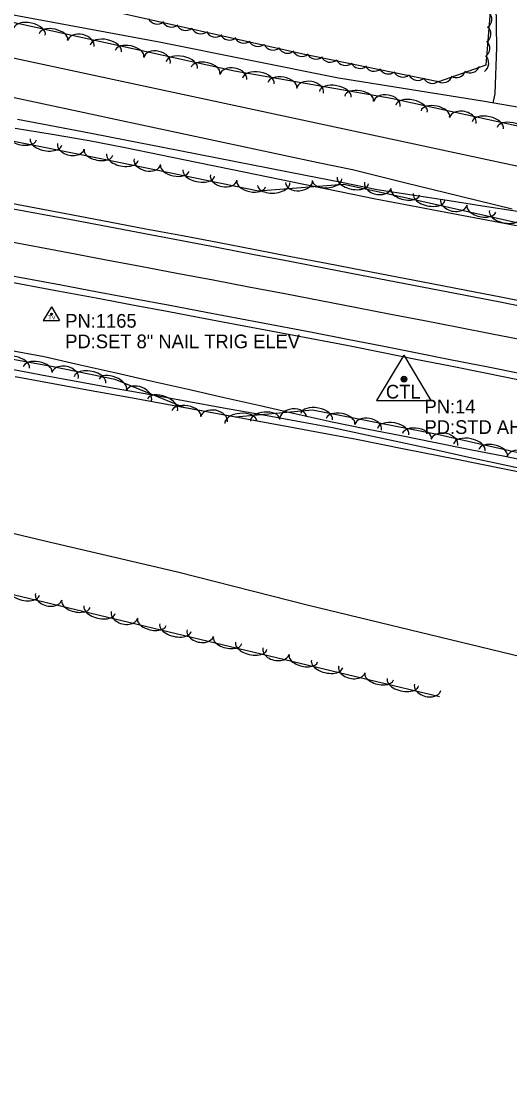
# Model space of a CAD drawing. Extents: x 1441650 to 1491889, y 345904 to 358319.
# Drawn here: x 1456782.8 to 1456961.1, y 351630.1 to 352014.8 of the extents above; entities that cross this region are included whole.
import ezdxf

# ---------------------------------------------------------------- set-up
doc = ezdxf.new("R2010")
doc.units = 0
for name, color, linetype in [('S_DITCHLINE', 7, 'Continuous'), ('S_EDGE_PAVEMENT', 7, 'Continuous'), ('S_PAVEMENT_CROWN', 7, 'Continuous'), ('S_PRIMARY_CTL', 7, 'Continuous'), ('S_PRIMARY_CTL_ANNOT', 7, 'Continuous'), ('S_SECONDARY_CTL', 7, 'Continuous'), ('S_SECONDARY_CTL_ANNOT', 7, 'Continuous'), ('S_SHOULDER', 7, 'Continuous'), ('S_STREAM', 7, 'Continuous'), ('S_TRAILS', 7, 'Continuous'), ('S_TREE', 7, 'Continuous'), ('S_WATER_UTILITIES', 7, 'Continuous')]:
    doc.layers.add(name, color=color, linetype=linetype)

msp = doc.modelspace()

# ---------------------------------------------------------------- linework, layer by layer
at = {"layer": 'S_DITCHLINE'}
for points in [[(1456781.58, 351979.01), (1456795, 351976.49), (1456808.42, 351973.98), (1456821.45, 351971.42), (1456834.49, 351968.85), (1456847.52, 351966.28), (1456860.55, 351963.72), (1456873.59, 351961.15), (1456886.62, 351958.58), (1456899.65, 351956.02), (1456912.68, 351953.45), (1456925.49, 351951.47), (1456938.3, 351949.49), (1456951.11, 351947.5), (1456963.92, 351945.52)], [(1456780.67, 351975.73), (1456794.2, 351973.53), (1456807.73, 351971.33), (1456820.78, 351968.67), (1456833.82, 351966), (1456846.87, 351963.33), (1456859.92, 351960.67), (1456872.97, 351958), (1456886.02, 351955.33), (1456899.07, 351952.67), (1456912.12, 351950), (1456924.96, 351947.57), (1456937.81, 351945.14), (1456950.66, 351942.71), (1456963.5, 351940.28)], [(1456777.96, 351894.89), (1456791.27, 351892.43), (1456804.39, 351889.45), (1456817.51, 351886.48), (1456830.63, 351883.51), (1456843.75, 351880.54), (1456856.87, 351877.56), (1456869.99, 351874.59), (1456883.12, 351871.62), (1456896.24, 351868.64), (1456908.83, 351866.13), (1456921.43, 351863.62), (1456934.03, 351861.11), (1456946.62, 351858.6), (1456959.22, 351856.09), (1456971.81, 351853.58)], [(1456776.87, 351888.36), (1456790.32, 351885.77), (1456803.58, 351883.38), (1456816.85, 351880.98), (1456830.12, 351878.59), (1456843.38, 351876.19), (1456856.65, 351873.79), (1456869.91, 351871.4), (1456883.18, 351869), (1456896.45, 351866.61), (1456908.88, 351863.91), (1456921.32, 351861.21), (1456933.76, 351858.5), (1456946.19, 351855.8), (1456958.63, 351853.1), (1456971.07, 351850.4)]]:
    msp.add_lwpolyline(points, dxfattribs=at)
at = {"layer": 'S_EDGE_PAVEMENT'}
for points in [[(1456778.58, 351946.61), (1456801.15, 351942.44), (1456814.57, 351939.9), (1456827.99, 351937.36), (1456841.41, 351934.82), (1456854.83, 351932.28), (1456867.86, 351929.74), (1456880.89, 351927.2), (1456893.92, 351924.67), (1456906.95, 351922.13), (1456919.61, 351919.71), (1456932.26, 351917.28), (1456944.92, 351914.86), (1456957.57, 351912.44), (1456970.03, 351909.93)], [(1456774.91, 351922.81), (1456797.44, 351918.6), (1456810.67, 351916.12), (1456823.9, 351913.65), (1456837.14, 351911.17), (1456850.37, 351908.69), (1456863.25, 351906.24), (1456876.13, 351903.78), (1456889.02, 351901.32), (1456901.9, 351898.86), (1456914.58, 351896.35), (1456927.27, 351893.83), (1456939.95, 351891.32), (1456952.64, 351888.8), (1456965.25, 351886.28)]]:
    msp.add_lwpolyline(points, dxfattribs=at)
at = {"layer": 'S_PAVEMENT_CROWN'}
msp.add_lwpolyline([(1456776.85, 351934.76), (1456800.01, 351930.39), (1456813.21, 351927.91), (1456826.42, 351925.43), (1456839.63, 351922.94), (1456852.84, 351920.46), (1456865.95, 351917.94), (1456879.06, 351915.42), (1456892.17, 351912.9), (1456905.29, 351910.38), (1456917.64, 351907.97), (1456930, 351905.57), (1456942.35, 351903.16), (1456954.7, 351900.75), (1456967.29, 351898.27)], dxfattribs=at)
at = {"layer": 'S_PRIMARY_CTL'}
for p, q in [((1456922.49, 351892.93), (1456912.46, 351876.42)), ((1456922.49, 351892.93), (1456932.31, 351876.42)), ((1456912.46, 351876.42), (1456932.31, 351876.42))]:
    msp.add_line(p, q, dxfattribs=at)
for radius in [1.04, 0.609, 0.344]:
    msp.add_circle((1456922.49, 351884.23), radius, dxfattribs=at)
at = {"layer": 'S_SECONDARY_CTL'}
for p, q in [((1456793.96, 351910.6), (1456790.95, 351905.64)), ((1456793.96, 351910.6), (1456796.91, 351905.64)), ((1456790.95, 351905.64), (1456796.91, 351905.64))]:
    msp.add_line(p, q, dxfattribs=at)
for radius in [0.311, 0.183, 0.103]:
    msp.add_circle((1456793.96, 351907.99), radius, dxfattribs=at)
at = {"layer": 'S_SHOULDER'}
for points in [[(1456779.26, 351948.41), (1456801.68, 351944.19), (1456815.03, 351941.65), (1456828.39, 351939.1), (1456841.75, 351936.56), (1456855.1, 351934.01), (1456868.16, 351931.5), (1456881.22, 351928.99), (1456894.29, 351926.47), (1456907.35, 351923.96), (1456919.97, 351921.52), (1456932.6, 351919.08), (1456945.23, 351916.64), (1456957.86, 351914.2), (1456970.43, 351911.7)], [(1456774.68, 351920.5), (1456796.91, 351916.32), (1456810.18, 351913.83), (1456823.44, 351911.34), (1456836.71, 351908.85), (1456849.97, 351906.36), (1456862.9, 351903.91), (1456875.83, 351901.46), (1456888.76, 351899.02), (1456901.69, 351896.57), (1456914.28, 351894.07), (1456926.87, 351891.56), (1456939.46, 351889.05), (1456952.05, 351886.54), (1456964.63, 351884.02)]]:
    msp.add_lwpolyline(points, dxfattribs=at)
at = {"layer": 'S_STREAM'}
msp.add_lwpolyline([(1456615.77, 351865.35), (1456695.66, 351848.16), (1456791.55, 351825.27), (1456839.87, 351813.99), (1456887.66, 351801.8), (1456991.3, 351776.75), (1457048.85, 351760.81), (1457118.67, 351745.25)], dxfattribs=at)
at = {"layer": 'S_TRAILS'}
for points in [[(1457268.76, 352049.42), (1457263.88, 352006.18), (1457257.72, 351978.65), (1457254.6, 351968.16), (1457245.15, 351954.83), (1457236.81, 351943.99), (1457223.45, 351940.54), (1457207.24, 351942.59), (1457150.06, 351951.48), (1457102.66, 351954.44), (1457056.72, 351964.71), (1457003.28, 351976.66), (1456951.11, 351985.66), (1456898.64, 351994), (1456833.2, 352007.16), (1456729.36, 352026.45), (1456653.98, 352040.61), (1456597.16, 352049.77), (1456529.59, 352059.81), (1456484.15, 352069.96), (1456466.33, 352073.63), (1456452.89, 352073.26), (1456447.05, 352071.68)], [(1456955.79, 352036.95), (1456956.2, 352005.22), (1456955.65, 351988.47), (1456954.84, 351984.84)]]:
    msp.add_lwpolyline(points, dxfattribs=at)
at = {"layer": 'S_TREE'}
for points in [[(1456527.22, 352219.77), (1456540.48, 352171.06), (1456547.01, 352136.18), (1456543.07, 352095.02), (1456540.96, 352069.62), (1456549.68, 352052.53), (1456572.48, 352046.22), (1456656.69, 352034.98), (1456766.41, 352017.4), (1456860.65, 351996.7), (1456917.81, 351986.67), (1456968.36, 351975.61), (1457003.67, 351974.34), (1457037, 351966.87), (1457091.18, 351954.76), (1457133.43, 351949.73), (1457169.05, 351946.81), (1457212.77, 351938.5), (1457241.33, 351937.88), (1457252.05, 351948.92), (1457259.75, 351971.53), (1457265.42, 351993.28), (1457268.88, 352004.52)], [(1456946.77, 352049.56), (1456954, 352019.61), (1456952.33, 351998.8), (1456935.11, 351992.63), (1456885.1, 352002.92), (1456810.32, 352019.63), (1456765.4, 352029.56), (1456649.16, 352049.43), (1456604.07, 352059.51), (1456562.66, 352066.04), (1456541.64, 352068)], [(1457347.72, 351846.82), (1457259.29, 351869.82), (1457150.71, 351895.35), (1457088.32, 351909.3), (1456973.99, 351938.99), (1456924.65, 351950.02), (1456900.56, 351955.26), (1456869.4, 351952.76), (1456813.77, 351964.27), (1456707.01, 351985.55), (1456663.97, 352001.96), (1456648.9, 352003.9), (1456628.29, 351995.91)], [(1456778.58, 351987.33), (1456791.1, 351984.66), (1456803.61, 351981.99), (1456816.12, 351979.32), (1456828.63, 351976.65), (1456841.14, 351973.98), (1456853.65, 351971.31), (1456866.17, 351968.64), (1456878.68, 351965.97), (1456891.19, 351963.3), (1456903.7, 351960.64), (1456923.13, 351955.87), (1456942.57, 351951.11), (1456962, 351946.35)], [(1456778.58, 351987.33), (1456791.1, 351984.66), (1456803.61, 351981.99), (1456816.12, 351979.32), (1456828.63, 351976.65), (1456841.14, 351973.98), (1456853.65, 351971.31), (1456866.17, 351968.64), (1456878.68, 351965.97), (1456891.19, 351963.3), (1456903.7, 351960.64), (1456923.13, 351955.87), (1456942.57, 351951.11), (1456962, 351946.35)], [(1456598.75, 351924.13), (1456686.06, 351910.97), (1456743.52, 351898.13), (1456793.9, 351888.95), (1456816.98, 351884.21), (1456842.02, 351874.01), (1456861.09, 351870.49), (1456889.07, 351872.98), (1456934.56, 351864.11), (1456964.71, 351857.37), (1457007.79, 351847.74), (1457051.75, 351837.91), (1457091.09, 351829.12), (1457165.52, 351812.48), (1457202.07, 351804.31), (1457267.07, 351790.49), (1457300, 351783.98), (1457347.16, 351770.87), (1457399.34, 351758.41), (1457426.78, 351748.95), (1457472.56, 351738.71), (1457528.33, 351726.24), (1457565.01, 351719.11), (1457614.77, 351707.89)], [(1456780.68, 351885.2), (1456794.51, 351882.66), (1456808.35, 351880.12), (1456822.18, 351877.59), (1456836.02, 351875.05), (1456849.85, 351872.51), (1456863.69, 351869.98), (1456877.52, 351867.44), (1456891.35, 351864.9), (1456905.19, 351862.36), (1456923.18, 351858.74), (1456941.17, 351855.11), (1456959.16, 351851.48), (1456977.15, 351847.85)], [(1456780.68, 351885.2), (1456794.51, 351882.66), (1456808.35, 351880.12), (1456822.18, 351877.59), (1456836.02, 351875.05), (1456849.85, 351872.51), (1456863.69, 351869.98), (1456877.52, 351867.44), (1456891.35, 351864.9), (1456905.19, 351862.36), (1456923.18, 351858.74), (1456941.17, 351855.11), (1456959.16, 351851.48), (1456977.15, 351847.85)], [(1456935.41, 351768.32), (1456757.49, 351810.91), (1456654.24, 351836.69), (1456612.99, 351855.17), (1456594.02, 351860.27), (1456573.25, 351864.94)]]:
    msp.add_lwpolyline(points, dxfattribs=at)
for centre, start, end in [((1456950.93, 352015.49), 304.6102, 46.2072), ((1456832.54, 352017.39), 206.6009, 308.1978), ((1456837.71, 352016.31), 206.6009, 308.1978), ((1456842.9, 352015.08), 206.6009, 308.1978), ((1456848.4, 352013.81), 206.6009, 308.1978), ((1456853.71, 352012.62), 206.6009, 308.1978), ((1456858.89, 352011.5), 206.6009, 308.1978), ((1456950.58, 352010.22), 304.6102, 46.2072), ((1456864.07, 352010.42), 206.6009, 308.1978), ((1456869.26, 352009.19), 206.6009, 308.1978), ((1456874.76, 352007.92), 206.6009, 308.1978), ((1456950.19, 352004.93), 304.6102, 46.2072), ((1456880.07, 352006.73), 206.6009, 308.1978), ((1456885.25, 352005.61), 206.6009, 308.1978), ((1456890.39, 352004.62), 207.5781, 309.175), ((1456949.75, 351999.5), 304.6102, 46.2072), ((1456895.61, 352003.47), 207.5781, 309.175), ((1456901.13, 352002.3), 207.5781, 309.175), ((1456906.46, 352001.2), 207.5781, 309.175), ((1456911.66, 352000.17), 207.5781, 309.175), ((1456946.58, 351999.57), 238.9264, 340.5233), ((1456916.85, 351999.18), 207.5781, 309.175), ((1456922.06, 351998.03), 207.5781, 309.175), ((1456927.58, 351996.86), 207.5781, 309.175), ((1456936.59, 351995.99), 238.9264, 340.5233), ((1456941.53, 351997.84), 238.9264, 340.5233), ((1456932.91, 351995.76), 207.5781, 309.175)]:
    msp.add_arc(centre, 3.64, start, end, dxfattribs=at)
for centre, major_axis, ratio, start_param, end_param in [((1456785.95, 352010.94), (-5.73, 1.26), 0.55008, 3.141593, 6.283185), ((1456794.61, 352009.04), (-5.22, 1.15), 0.540699, 3.141593, 6.283185), ((1456804.62, 352006.57), (-4.84, 1.06), 0.685311, 3.141593, 6.283185), ((1456813.72, 352004.84), (-5.73, 1.26), 0.55008, 3.141593, 6.283185), ((1456822.38, 352002.94), (-5.22, 1.15), 0.540699, 3.141593, 6.283185), ((1456832.39, 352000.47), (-4.84, 1.06), 0.685311, 3.141593, 6.283185), ((1456841.48, 351998.74), (-5.73, 1.26), 0.55008, 3.141593, 6.283185), ((1456850.15, 351996.84), (-5.22, 1.15), 0.540699, 3.141593, 6.283185), ((1456860.25, 351994.35), (-4.88, 0.86), 0.685311, 3.141593, 6.283185), ((1456869.41, 351993.01), (-5.78, 1.01), 0.55008, 3.141593, 6.283185), ((1456878.15, 351991.48), (-5.27, 0.92), 0.540699, 3.141593, 6.283185), ((1456888.25, 351989.44), (-4.88, 0.86), 0.685311, 3.141593, 6.283185), ((1456897.41, 351988.09), (-5.78, 1.01), 0.55008, 3.141593, 6.283185), ((1456906.15, 351986.56), (-5.27, 0.92), 0.540699, 3.141593, 6.283185), ((1456916.25, 351984.52), (-4.88, 0.86), 0.685311, 3.141593, 6.283185), ((1456925.26, 351982.86), (-5.73, 1.25), 0.550095, 3.141595, 6.283187), ((1456933.92, 351980.97), (-5.22, 1.14), 0.540714, 3.141595, 6.283187), ((1456943.93, 351978.51), (-4.84, 1.06), 0.685329, 3.141596, 6.283189), ((1456953.03, 351976.79), (-5.73, 1.25), 0.550095, 3.141595, 6.283187), ((1456961.69, 351974.89), (-5.22, 1.14), 0.540714, 3.141595, 6.283187), ((1456783.2, 351972.51), (5.24, -1.05), 0.536291, 3.141565, 6.283158), ((1456791.9, 351970.77), (5.76, -1.15), 0.545595, 3.141564, 6.283157), ((1456801.03, 351969.22), (4.86, -0.97), 0.679723, 3.141546, 6.283139), ((1456811.08, 351966.95), (5.24, -1.05), 0.536291, 3.141565, 6.283158), ((1456819.78, 351965.17), (5.75, -1.19), 0.545599, 3.141538, 6.283131), ((1456828.9, 351963.55), (4.85, -1), 0.679728, 3.141504, 6.283096), ((1456838.94, 351961.21), (5.24, -1.08), 0.536295, 3.14154, 6.283132), ((1456847.62, 351959.41), (5.75, -1.19), 0.545599, 3.141538, 6.283131), ((1456856.74, 351957.79), (4.85, -1), 0.679728, 3.141504, 6.283096), ((1456866.78, 351955.45), (5.24, -1.08), 0.536295, 3.14154, 6.283132), ((1456874.97, 351955.31), (5.85, 0.48), 0.545931, 3.139332, 6.280925), ((1456884.18, 351956.31), (4.94, 0.41), 0.68014, 3.137914, 6.279506), ((1456894.46, 351956.88), (5.33, 0.43), 0.536621, 3.139402, 6.280995), ((1456903.86, 351956.69), (5.73, -1.24), 0.545725, 3.139485, 6.281078), ((1456912.96, 351954.98), (4.84, -1.04), 0.679883, 3.138164, 6.279757), ((1456922.97, 351952.53), (5.22, -1.13), 0.536419, 3.13955, 6.281143), ((1456931.63, 351950.61), (5.73, -1.28), 0.545634, 3.140627, 6.28222), ((1456940.72, 351948.84), (4.84, -1.08), 0.679772, 3.140022, 6.281615), ((1456950.72, 351946.34), (5.22, -1.16), 0.53633, 3.140657, 6.28225), ((1456959.37, 351944.41), (5.73, -1.28), 0.545634, 3.140627, 6.28222), ((1456780.14, 351889.31), (-5.77, 1.05), 0.546951, 3.141593, 6.283185), ((1456788.86, 351887.73), (-5.26, 0.96), 0.537624, 3.141593, 6.283185), ((1456798.87, 351885.51), (-4.85, 1), 0.68142, 3.141143, 6.282736), ((1456807.99, 351883.9), (-5.75, 1.18), 0.546957, 3.141317, 6.28291), ((1456816.3, 351882.21), (-4.95, 2.02), 0.53776, 3.141593, 6.283185), ((1456825.74, 351878.08), (-4.59, 1.87), 0.681585, 3.141593, 6.283185), ((1456834.42, 351874.82), (-5.43, 2.21), 0.547089, 3.141593, 6.283185), ((1456843.13, 351871.66), (-5.26, 0.97), 0.537625, 3.141593, 6.283185), ((1456853.21, 351869.53), (-4.87, 0.9), 0.681414, 3.141593, 6.283185), ((1456862.96, 351868.54), (-5.85, -0.52), 0.547162, 3.141593, 6.283185), ((1456871.79, 351869.33), (-5.33, -0.47), 0.537831, 3.141593, 6.283185), ((1456882.07, 351869.98), (-4.94, -0.44), 0.681676, 3.141593, 6.283185), ((1456890.65, 351870.53), (-5.76, 1.12), 0.546952, 3.141593, 6.283185), ((1456899.35, 351868.83), (-5.25, 1.02), 0.537625, 3.141593, 6.283185), ((1456909.42, 351866.6), (-4.86, 0.95), 0.681415, 3.141593, 6.283185), ((1456918.55, 351865.08), (-5.76, 1.12), 0.546952, 3.141593, 6.283185), ((1456927.26, 351863.38), (-5.25, 1.02), 0.537625, 3.141593, 6.283185), ((1456937.24, 351861.08), (-4.84, 1.08), 0.681421, 3.141593, 6.283185), ((1456946.33, 351859.31), (-5.73, 1.28), 0.546958, 3.141593, 6.283185), ((1456954.98, 351857.38), (-5.22, 1.17), 0.537631, 3.141593, 6.283185), ((1456964.98, 351854.88), (-4.84, 1.08), 0.681421, 3.141593, 6.283185), ((1456783.85, 351806.78), (5.71, -1.37), 0.549745, 3.141752, 6.283345), ((1456792.91, 351804.88), (4.82, -1.15), 0.684894, 3.141854, 6.283447), ((1456802.87, 351802.23), (5.2, -1.25), 0.540371, 3.141747, 6.28334), ((1456811.49, 351800.16), (5.71, -1.37), 0.549745, 3.141752, 6.283345), ((1456820.56, 351798.26), (4.82, -1.15), 0.684894, 3.141854, 6.283447), ((1456830.51, 351795.61), (5.2, -1.25), 0.540371, 3.141747, 6.28334), ((1456839.14, 351793.55), (5.71, -1.37), 0.549745, 3.141752, 6.283345), ((1456848.2, 351791.64), (4.82, -1.15), 0.684894, 3.141854, 6.283447), ((1456858.16, 351788.99), (5.2, -1.25), 0.540371, 3.141747, 6.28334), ((1456866.78, 351786.93), (5.71, -1.37), 0.549745, 3.141752, 6.283345), ((1456875.85, 351785.03), (4.82, -1.15), 0.684894, 3.141854, 6.283447), ((1456885.81, 351782.37), (5.2, -1.25), 0.540371, 3.141747, 6.28334), ((1456894.43, 351780.31), (5.71, -1.37), 0.549745, 3.141752, 6.283345), ((1456903.49, 351778.41), (4.82, -1.15), 0.684894, 3.141854, 6.283447), ((1456913.45, 351775.76), (5.2, -1.25), 0.540371, 3.141747, 6.28334), ((1456922.08, 351773.69), (5.71, -1.37), 0.549745, 3.141752, 6.283345), ((1456931.14, 351771.79), (4.82, -1.15), 0.684894, 3.141854, 6.283447)]:
    msp.add_ellipse(centre, major_axis=major_axis, ratio=ratio, start_param=start_param, end_param=end_param, dxfattribs=at)
at = {"layer": 'S_WATER_UTILITIES'}
msp.add_line((1456494.84, 352062.52), (1458511.04, 351630.06), dxfattribs=at)

# ---------------------------------------------------------------- texts
at = {"layer": 'S_PRIMARY_CTL'}
msp.add_text('CTL', height=5, rotation=360, dxfattribs=at).set_placement((1456915.9, 351877.15))
at = {"layer": 'S_PRIMARY_CTL_ANNOT'}
for s, p in [('PN:14', (1456929.99, 351871.73)), ('PD:STD AHTD MON.STAMPED PN:14 JOB 050264', (1456929.99, 351864.23))]:
    msp.add_text(s, height=5, dxfattribs=at).set_placement(p)
at = {"layer": 'S_SECONDARY_CTL'}
msp.add_text('TV', height=1.5, rotation=360, dxfattribs=at).set_placement((1456792.76, 351905.98))
at = {"layer": 'S_SECONDARY_CTL_ANNOT'}
for s, p in [('PN:1165', (1456798.96, 351902.99)), ('PD:SET 8" NAIL TRIG ELEV', (1456798.96, 351895.49))]:
    msp.add_text(s, height=5, dxfattribs=at).set_placement(p)

doc.saveas('drawing.dxf')
